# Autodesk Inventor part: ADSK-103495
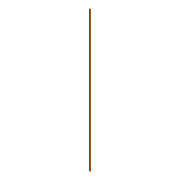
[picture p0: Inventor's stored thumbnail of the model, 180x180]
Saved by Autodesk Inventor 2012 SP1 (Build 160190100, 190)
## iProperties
Shininess: 0.0
Created: 2000-10
Part Number: ADSK-103495
Document SubType Name: Modeling
Designer: Administrator
Stock Number: ADSK-103495
Density: 1 g/cm^3
Material: Default
Density: 0.0
Volumn: 0.0
Area: 0.0
PropertySet Name: Model Information
Control State: 0
Master: False
Checked Out: False
Author: Administrator
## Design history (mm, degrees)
node "Extrusion1" dims "d2" = 4.7752, "d3" = 0
  sketch "Sketch1"
    geometry: L1 (-37.57, 1498.065)-(-24.87, 1498.065); L2 (-24.87, 1498.065)-(-24.87, -25.935); L3 (-24.87, -25.935)-(-37.57, -25.935); L4 (-37.57, -25.935)-(-37.57, 1498.065)
    constraints: 8 end point, 2 parallel, 1 horizontal, 1 perpendicular
    dimensions: "d0" = 1524 distance of L3.end L1.start; "d1" = 12.7 distance of L2.end L3.end
node "Extrusion2" dims "d7" = 2032, "d8" = 0
  sketch "Sketch2"
    geometry: L1 (12.7, 0)-(12.7, -4.775) reference; L2 (12.7, 0)-(0, 0) reference; L3 (12.7, 0)-(13.782, 0); L4 (13.782, -4.775)-(12.7, -4.775); L5 (12.7, -4.775)-(12.7, 0); L6 (0, -4.775)-(12.7, -4.775) reference; C1 r 1.587 at (15.875, -2.388); A1 r 3.175 centre (15.875, -2.388) between (13.782, -4.775) and (13.782, 0)
    constraints: 6 end point, 2 centre point, 2 parallel, 2 point on circle, 1 horizontal, 1 point on line, 1 tangent
    dimensions: "d4" = 3.175 horizontal distance of L1.start C1.centre; "d6" = 3.175 diameter of C1; "d9" = 0 distance between parallel lines of L6 L4; "d10" = 0 distance of L4.end L1.end; "d11" = 2.3876 distance from line of L2 C1.centre
body "Solid1"
